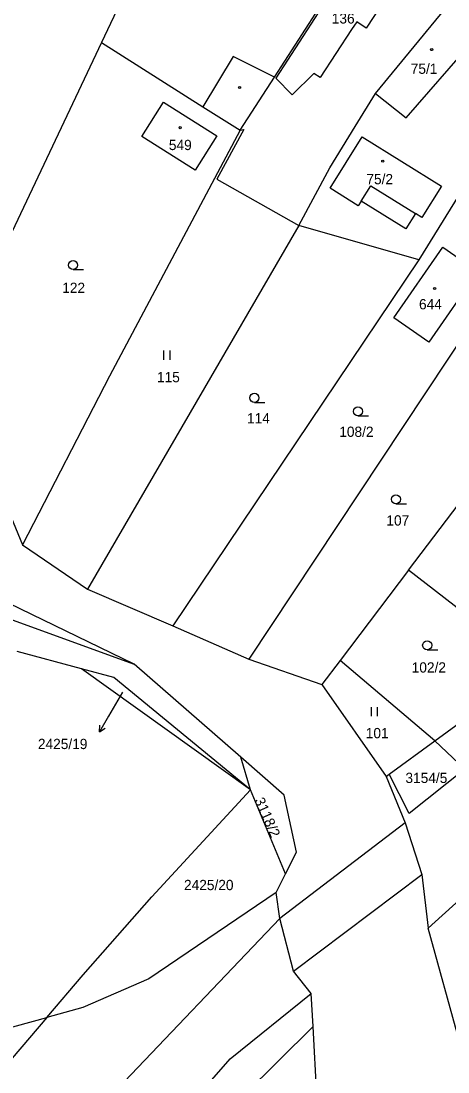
# Model space of a CAD drawing. Extents: x -755528 to -748832, y -1118122 to -1111095.
# Drawn here: x -753482.8 to -753412, y -1115665 to -1115490.8 of the extents above; entities that cross this region are included whole.
import ezdxf

# ---------------------------------------------------------------- set-up
doc = ezdxf.new("R2010")
doc.units = 0
for name, color, linetype in [('DZ_DO_ostatní', 7, 'Continuous'), ('DZ_DO_PUPFL', 7, 'Continuous'), ('DZ_NAD_ZPF', 7, 'Continuous'), ('legenda barvy', 7, 'Continuous'), ('legenda_text', 7, 'Continuous'), ('TZ_UMVŽST', 7, 'Continuous')]:
    doc.layers.add(name, color=color, linetype=linetype)

msp = doc.modelspace()

# ---------------------------------------------------------------- linework, layer by layer
at = {"layer": 'DZ_DO_ostatní'}
for p, q in [((-753432.82, -1115488.39), (-753440.58, -1115500.3)), ((-753422.91, -1115488), (-753425.56, -1115492.01)), ((-753427.15, -1115490.97), (-753427.99, -1115492.25)), ((-753425.56, -1115492.01), (-753427.15, -1115490.97)), ((-753427.99, -1115492.25), (-753433.23, -1115500.21)), ((-753418.93, -1115506.88), (-753405.72, -1115491.69)), ((-753447.67, -1115496.69), (-753452.67, -1115505.05)), ((-753440.77, -1115500.11), (-753447.67, -1115496.69)), ((-753434.28, -1115499.52), (-753437.88, -1115503.05)), ((-753433.23, -1115500.21), (-753434.28, -1115499.52)), ((-753437.88, -1115503.05), (-753440.58, -1115500.3)), ((-753424, -1115502.82), (-753418.93, -1115506.88)), ((-753426.4, -1115520.66), (-753424.79, -1115518.14)), ((-753424.79, -1115518.14), (-753417.41, -1115522.72)), ((-753419.11, -1115623.69), (-753439.88, -1115639.55)), ((-753437.61, -1115648.23), (-753416.36, -1115632.25))]:
    msp.add_line(p, q, dxfattribs=at)
at = {"layer": 'DZ_NAD_ZPF'}
for p, q in [((-753465.64, -1115486.23), (-753469.5, -1115494.37)), ((-753469.5, -1115494.37), (-753494.92, -1115548.02)), ((-753408.3, -1115516.62), (-753416.84, -1115530.42)), ((-753436.75, -1115524.68), (-753471.82, -1115584.97)), ((-753416.84, -1115530.42), (-753436.75, -1115524.68)), ((-753416.84, -1115530.42), (-753457.68, -1115591.04)), ((-753408.44, -1115541.42), (-753445.02, -1115596.57)), ((-753494.92, -1115548.02), (-753482.6, -1115577.61)), ((-753418.53, -1115581.79), (-753397.6, -1115554.24)), ((-753482.6, -1115577.61), (-753471.82, -1115584.97)), ((-753418.53, -1115581.79), (-753429.91, -1115596.76)), ((-753397.63, -1115598.03), (-753418.53, -1115581.79)), ((-753506.18, -1115582.06), (-753464.09, -1115597.4)), ((-753471.82, -1115584.97), (-753457.68, -1115591.04)), ((-753464.09, -1115597.4), (-753487.15, -1115586.2)), ((-753457.68, -1115591.04), (-753445.02, -1115596.57)), ((-753472.8, -1115598.14), (-753483.46, -1115595.27)), ((-753446.38, -1115612.82), (-753464.09, -1115597.4)), ((-753445.02, -1115596.57), (-753432.94, -1115600.74)), ((-753429.91, -1115596.76), (-753432.94, -1115600.74)), ((-753414.19, -1115610.11), (-753429.91, -1115596.76)), ((-753444.78, -1115618.23), (-753472.8, -1115598.14)), ((-753414.19, -1115610.11), (-753397.63, -1115598.03)), ((-753432.94, -1115600.74), (-753422.27, -1115616.01)), ((-753421.76, -1115615.64), (-753414.19, -1115610.11)), ((-753414.19, -1115610.11), (-753409.19, -1115614.8)), ((-753444.78, -1115618.23), (-753446.38, -1115612.82)), ((-753422.27, -1115616.01), (-753421.76, -1115615.64)), ((-753438.94, -1115632.11), (-753444.78, -1115618.23)), ((-753440.52, -1115635.23), (-753438.94, -1115632.11)), ((-753439.88, -1115639.55), (-753440.52, -1115635.23)), ((-753410.11, -1115636.42), (-753415.28, -1115641.14)), ((-753478.07, -1115679.5), (-753439.88, -1115639.55)), ((-753434.39, -1115657.4), (-753434.69, -1115651.96)), ((-753478.54, -1115655.91), (-753484.31, -1115662.65)), ((-753433.52, -1115673.02), (-753434.39, -1115657.4))]:
    msp.add_line(p, q, dxfattribs=at)
for points in [[(-753446.46, -1115508.92), (-753440.77, -1115500.11), (-753425.38, -1115476.24)], [(-753436.75, -1115524.68), (-753431.6, -1115515.17), (-753427.42, -1115508.28), (-753424, -1115502.82), (-753411.2, -1115487.19)], [(-753469.5, -1115494.37), (-753452.67, -1115505.05), (-753446.46, -1115508.92)], [(-753462.78, -1115509.95), (-753459.22, -1115504.28), (-753450.37, -1115509.86), (-753453.97, -1115515.55), (-753462.78, -1115509.95)], [(-753446.46, -1115508.92), (-753468.15, -1115549.65), (-753482.6, -1115577.61)], [(-753446.46, -1115508.92), (-753445.89, -1115508.81), (-753450.36, -1115517.02), (-753436.75, -1115524.68)], [(-753416.32, -1115523.4), (-753417.41, -1115522.72), (-753419.02, -1115525.27), (-753426.4, -1115520.66), (-753426.89, -1115521.43), (-753431.55, -1115518.51), (-753426.23, -1115510), (-753413.09, -1115518.19), (-753416.32, -1115523.4)], [(-753415.15, -1115544.03), (-753420.96, -1115540), (-753412.83, -1115528.3), (-753407.02, -1115532.32), (-753415.15, -1115544.03)], [(-753444.78, -1115618.23), (-753467.43, -1115599.59), (-753472.8, -1115598.14)], [(-753438.94, -1115632.11), (-753437.13, -1115628.54), (-753439.19, -1115619.07), (-753446.38, -1115612.82)], [(-753409.19, -1115614.8), (-753418.46, -1115622.14), (-753421.76, -1115615.64)], [(-753422.27, -1115616.01), (-753419.11, -1115623.69), (-753416.36, -1115632.25), (-753415.28, -1115641.14)], [(-753478.54, -1115655.91), (-753472.51, -1115648.87), (-753461.16, -1115635.93), (-753444.78, -1115618.23)], [(-753440.52, -1115635.23), (-753461.65, -1115649.52), (-753472.56, -1115654.26), (-753478.54, -1115655.91)], [(-753434.69, -1115651.96), (-753437.61, -1115648.23), (-753439.88, -1115639.55)], [(-753399.68, -1115682.5), (-753402.64, -1115678.68), (-753407.83, -1115669.01), (-753410.02, -1115660.14), (-753415.28, -1115641.14)], [(-753472.17, -1115700.58), (-753461.53, -1115681.87), (-753455.43, -1115671.14), (-753448.13, -1115662.76), (-753434.69, -1115651.96)], [(-753492.76, -1115659.07), (-753488.67, -1115658.7), (-753478.54, -1115655.91)], [(-753461.04, -1115685.36), (-753457.44, -1115680.21), (-753434.39, -1115657.4)]]:
    msp.add_lwpolyline(points, dxfattribs=at)
at = {"layer": 'legenda barvy'}
for p, q in [((-753466, -1115602.05), (-753468.33, -1115606.02)), ((-753468.33, -1115606.02), (-753469.83, -1115608.619)), ((-753469.83, -1115608.619), (-753469.763, -1115607.501)), ((-753469.83, -1115608.619), (-753468.896, -1115608.002))]:
    msp.add_line(p, q, dxfattribs=at)
at = {"layer": 'legenda_text'}
for centre in [(-753414.7068, -1115495.5592), (-753446.5768, -1115501.8292), (-753456.4268, -1115508.4892), (-753422.8268, -1115514.0592), (-753414.2168, -1115535.1392)]:
    msp.add_circle(centre, 0.175, dxfattribs=at)
at = {"layer": 'TZ_UMVŽST'}
for p, q in [((-753474.203, -1115532.02), (-753472.453, -1115532.02)), ((-753459.121, -1115546.94), (-753459.121, -1115545.44)), ((-753458.12, -1115546.94), (-753458.12, -1115545.44)), ((-753444.113, -1115554.01), (-753442.363, -1115554.01)), ((-753426.943, -1115556.25), (-753425.193, -1115556.25)), ((-753420.643, -1115570.82), (-753418.893, -1115570.82)), ((-753415.453, -1115595.01), (-753413.703, -1115595.01)), ((-753424.681, -1115606.02), (-753424.681, -1115604.52)), ((-753423.68, -1115606.02), (-753423.68, -1115604.52))]:
    msp.add_line(p, q, dxfattribs=at)
for centre in [(-753474.2029, -1115531.2698), (-753444.1129, -1115553.2598), (-753426.9429, -1115555.4998), (-753420.6429, -1115570.0698), (-753415.4529, -1115594.2598)]:
    msp.add_circle(centre, 0.75, dxfattribs=at)

# ---------------------------------------------------------------- texts
at = {"layer": 'DZ_DO_PUPFL'}
for s, p in [('136', (-753431.28, -1115491.24)), ('75/1', (-753418.179, -1115499.58)), ('549', (-753458.31, -1115512.21)), ('75/2', (-753425.539, -1115517.87)), ('122', (-753476.01, -1115535.88)), ('644', (-753416.805, -1115538.6)), ('115', (-753460.29, -1115550.68)), ('114', (-753445.35, -1115557.5)), ('108/2', (-753430.04, -1115559.73)), ('107', (-753422.22, -1115574.42)), ('102/2', (-753418.02, -1115598.78)), ('101', (-753425.64, -1115609.66)), ('2425/19', (-753480.043, -1115611.458)), ('3154/5', (-753419.06, -1115617.08)), ('2425/20', (-753455.8, -1115634.83))]:
    msp.add_text(s, height=1.7, dxfattribs=at).set_placement(p)
msp.add_text('3118/2', height=1.7, rotation=294, dxfattribs=at).set_placement((-753444.146, -1115619.925))

doc.saveas('drawing.dxf')
